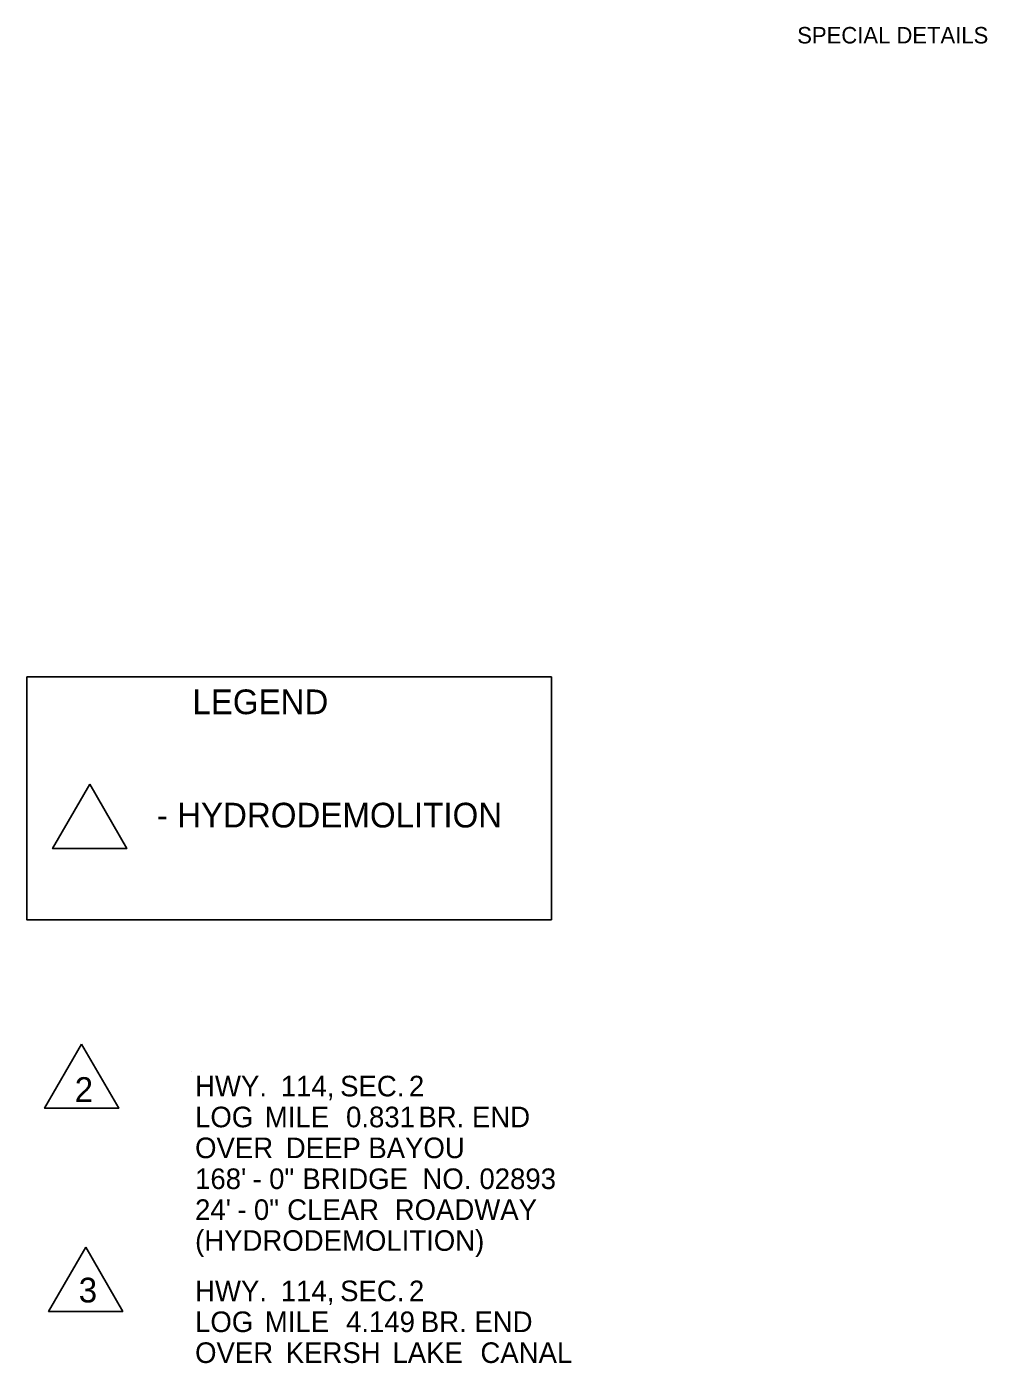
# Model space of a CAD drawing. Extents: x -33639 to 34530, y -17264 to 5867.
# Drawn here: x -6220 to -2722, y -12310 to -7443 of the extents above; entities that cross this region are included whole.
import ezdxf

# ---------------------------------------------------------------- set-up
doc = ezdxf.new("R2010")
doc.units = 0
for name, color, linetype in [('Default', 7, 'Continuous'), ('R_Annotation', 7, 'Continuous'), ('R_Border', 7, 'Continuous'), ('S_MISC_BOUNDARY', 7, 'Continuous')]:
    doc.layers.add(name, color=color, linetype=linetype)

msp = doc.modelspace()

# ---------------------------------------------------------------- linework, layer by layer
at = {"layer": 'R_Annotation'}
for points in [[(-6219.6, -9810.4), (-4309, -9810.4), (-4309, -10695), (-6219.6, -10695)], [(-5990.3, -10201.6), (-5855.3, -10435.4), (-6125.3, -10435.4)], [(-6019.6, -11147.8), (-5884.6, -11381.6), (-6154.6, -11381.6)], [(-6019.6, -11147.8), (-5884.6, -11381.6), (-6154.6, -11381.6)], [(-6004.8, -11887.7), (-5869.8, -12121.5), (-6139.8, -12121.5)]]:
    msp.add_lwpolyline(points, close=True, dxfattribs=at)
at = {"layer": 'S_MISC_BOUNDARY'}
msp.add_line((-5621.2, -11248.1), (-5621.2, -11248.1), dxfattribs=at)

# ---------------------------------------------------------------- texts
at = {"layer": 'Default'}
for s, p in [('HWY.', (-5606.6, -11338.1)), (' 114,', (-5322.3, -11338.1)), (' SEC.', (-5106.3, -11338.1)), (' 2', (-4855.8, -11338.1)), ('LOG', (-5606.6, -11450.6)), (' MILE', (-5380.6, -11450.6)), (' 0.831', (-5084.8, -11450.6)), (' BR.', (-4821.4, -11450.6)), (' END', (-4626.2, -11450.6)), ('OVER', (-5606.6, -11563.1)), (' BAYOU', (-5003.6, -11563.1)), (' DEEP', (-5304.2, -11563.1)), ("168'", (-5606.6, -11675.6)), (' 0"', (-5364.9, -11675.6)), (' BRIDGE', (-5243.9, -11675.6)), (' NO.', (-4806.5, -11675.6)), (' 02893', (-4599.1, -11675.6)), (' -', (-5425.1, -11675.6)), ("24'", (-5606.6, -11788.1)), (' 0"', (-5420.3, -11788.1)), (' CLEAR', (-5299.3, -11788.1)), (' ROADWAY', (-4907.6, -11788.1)), (' -', (-5480.5, -11788.1)), ('(HYDRODEMOLITION)', (-5606.6, -11900.6)), ('HWY.', (-5606.6, -12084)), (' 114,', (-5322.3, -12084)), (' SEC.', (-5106.3, -12084)), (' 2', (-4855.8, -12084)), ('LOG', (-5606.6, -12196.5)), (' MILE', (-5380.6, -12196.5)), (' 4.149', (-5084.8, -12196.5)), (' BR.', (-4812.6, -12196.5)), (' END', (-4617.4, -12196.5)), ('OVER', (-5606.6, -12309)), (' KERSH', (-5304.2, -12309)), (' LAKE', (-4915.7, -12309)), (' CANAL', (-4595.4, -12309))]:
    msp.add_text(s, height=75, dxfattribs=at).set_placement(p)
at = {"layer": 'R_Annotation'}
for s, p in [('LEGEND', (-5616.3, -9946.2)), ('- HYDRODEMOLITION', (-5745.5, -10358.8)), ('2', (-6045, -11358.2)), ('3', (-6030.3, -12088.6))]:
    msp.add_text(s, height=90, dxfattribs=at).set_placement(p)
at = {"layer": 'R_Border'}
msp.add_text('SPECIAL DETAILS', height=60, dxfattribs=at).set_placement((-3413.9, -7503.5))

doc.saveas('drawing.dxf')
